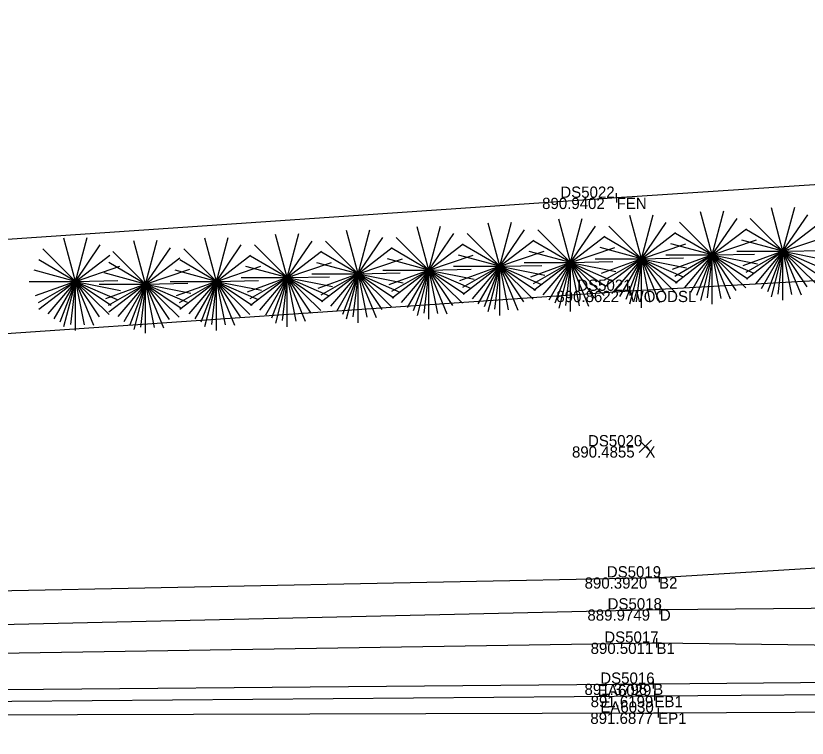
# Model space of a CAD drawing. Extents: x 179044 to 189691, y 286531 to 301257.
# Drawn here: x 179702.4 to 179786.9, y 300591.8 to 300668.9 of the extents above; entities that cross this region are included whole.
import ezdxf

# ---------------------------------------------------------------- set-up
doc = ezdxf.new("R2010")
doc.units = 0
for name, color, linetype in [('DR_X_Ditch', 7, 'Continuous'), ('PV_X_EOP', 7, 'Continuous'), ('PV_X_Shoulder_Aggregate', 7, 'Continuous'), ('RD_X_Fence', 7, 'Continuous'), ('SV_X_Break_Lines', 7, 'Continuous'), ('SV_X_Random_Point', 7, 'Continuous'), ('SV_X_Shot_Marker', 7, 'Continuous'), ('SV_X_Text_Comment', 7, 'Continuous'), ('SV_X_Text_Elevation', 7, 'Continuous'), ('SV_X_Text_Name', 7, 'Continuous'), ('VG_X_Cells', 7, 'Continuous'), ('VG_X_Text', 7, 'Continuous'), ('VG_X_Tree_Line_Rt', 7, 'Continuous')]:
    doc.layers.add(name, color=color, linetype=linetype)

msp = doc.modelspace()

# ---------------------------------------------------------------- linework, layer by layer
at = {"layer": 'DR_X_Ditch'}
msp.add_lwpolyline([(179564.56, 300599.962), (179672.339, 300603.26), (179771.172, 300605.494), (179880.337, 300606.441), (179984.937, 300607.328), (180077.947, 300608.965), (180127.19, 300616.843), (180132.045, 300619.573), (180144.286, 300623.545), (180155.547, 300629.29), (180160.465, 300633.547)], dxfattribs=at)
at = {"layer": 'PV_X_EOP'}
msp.add_lwpolyline([(179370.831, 300591.751), (179475.585, 300592.875), (179659.265, 300594.122), (179770.991, 300594.472), (179880.742, 300594.985), (179984.71, 300595.495), (180079.288, 300595.313), (180129.921, 300597.382), (180139.474, 300598.239), (180154.233, 300602.666), (180170.463, 300611.587), (180179.633, 300620.691), (180184.59, 300626.615), (180188.342, 300633.535), (180190.62, 300639.725), (180171.316, 300693.382), (180137.201, 300785.062), (180098.417, 300888.791)], dxfattribs=at)
at = {"layer": 'PV_X_Shoulder_Aggregate'}
msp.add_lwpolyline([(179563.565, 300594.924), (179658.987, 300595.359), (179770.596, 300596.259), (179881.565, 300597.129), (179984.257, 300597.357), (180079.139, 300597.322), (180129.307, 300600.299), (180139.964, 300601.425), (180153.02, 300605.118), (180169.97, 300613.883), (180177.635, 300623.691), (180181.654, 300635.111), (180182.998, 300649.235), (180167.771, 300692.69), (180134.639, 300784.201), (180095.484, 300888.508)], dxfattribs=at)
at = {"layer": 'RD_X_Fence'}
msp.add_lwpolyline([(180033.616, 300896.161), (180069.423, 300800.637), (180103.118, 300709.458), (180117.129, 300674.9), (180112.616, 300673.011), (180037.359, 300667.77), (179974.547, 300663.799), (179875.902, 300656.609), (179766.558, 300649.439), (179668.068, 300642.7), (179565.54, 300636.358)], dxfattribs=at)
at = {"layer": 'SV_X_Break_Lines'}
for points in [[(179564.638, 300606.986), (179671.768, 300606.922), (179771.087, 300608.912), (179880.599, 300615.611), (179986.884, 300616.02), (180078.033, 300615.521), (180124.742, 300624.492), (180128.289, 300624.221), (180137.303, 300629.118), (180148.459, 300633.708), (180154.503, 300636.496), (180146.307, 300651.241), (180135.969, 300673.811), (180118.542, 300716.074), (180095.911, 300772.35), (180076.611, 300824.96), (180047.5, 300900.199)], [(179564.191, 300598.682), (179770.809, 300601.942), (179880.33, 300600.557), (179984.707, 300602.17), (180076.298, 300602.513), (180129.447, 300605.473), (180133.823, 300610.665), (180143.543, 300612.063), (180154.911, 300619.358), (180168.807, 300625.749), (180172.898, 300631.66), (180174.527, 300641.071), (180168.307, 300660.619), (180157.537, 300688.57), (180123.865, 300779.294), (180087.271, 300883.216)], [(179564.385, 300595.92), (179672.75, 300596.68), (179770.459, 300597.562), (179880.51, 300598.544), (179984.703, 300599.007), (180076.342, 300598.773), (180129.476, 300602.027), (180135.94, 300603.814), (180151.807, 300606.879), (180162.976, 300612.722)]]:
    msp.add_lwpolyline(points, dxfattribs=at)
at = {"layer": 'SV_X_Random_Point'}
for p, q in [((179768.958, 300622.237), (179770.291, 300623.572)), ((179768.958, 300623.572), (179770.291, 300622.237))]:
    msp.add_line(p, q, dxfattribs=at)
at = {"layer": 'SV_X_Shot_Marker'}
for p, q in [((179766.591, 300648.94), (179766.526, 300649.938)), ((179767.057, 300649.471), (179766.059, 300649.406)), ((179766.558, 300649.439), (179766.558, 300649.439)), ((179767.436, 300639.47), (179768.434, 300639.538)), ((179767.901, 300640.003), (179767.969, 300639.005)), ((179767.935, 300639.504), (179767.935, 300639.504)), ((179770.587, 300608.902), (179771.587, 300608.922)), ((179771.077, 300609.412), (179771.097, 300608.412)), ((179771.087, 300608.912), (179771.087, 300608.912)), ((179771.161, 300605.994), (179771.183, 300604.994)), ((179770.672, 300605.483), (179771.672, 300605.505)), ((179771.172, 300605.494), (179771.172, 300605.494)), ((179770.801, 300602.442), (179770.816, 300601.442)), ((179770.309, 300601.934), (179771.309, 300601.95)), ((179770.809, 300601.942), (179770.809, 300601.942)), ((179770.454, 300598.062), (179770.463, 300597.062)), ((179769.959, 300597.558), (179770.959, 300597.567)), ((179770.459, 300597.562), (179770.459, 300597.562)), ((179770.096, 300596.255), (179771.096, 300596.263)), ((179770.592, 300596.759), (179770.6, 300595.759)), ((179770.596, 300596.259), (179770.596, 300596.259)), ((179770.99, 300594.972), (179770.993, 300593.972)), ((179770.491, 300594.47), (179771.491, 300594.474)), ((179770.991, 300594.472), (179770.991, 300594.472))]:
    msp.add_line(p, q, dxfattribs=at)
at = {"layer": 'VG_X_Cells'}
for p, q in [((179776.76, 300643.334), (179775.525, 300647.947)), ((179776.76, 300643.334), (179778.016, 300648.032)), ((179784.326, 300643.736), (179783.091, 300648.35)), ((179784.326, 300643.736), (179785.582, 300648.435)), ((179761.627, 300642.529), (179760.392, 300647.143)), ((179761.627, 300642.529), (179762.884, 300647.228)), ((179769.193, 300642.932), (179767.958, 300647.545)), ((179769.193, 300642.932), (179770.45, 300647.63)), ((179776.76, 300643.334), (179779.415, 300647.219)), ((179784.326, 300643.736), (179780.836, 300647.223)), ((179784.326, 300643.736), (179786.981, 300647.621)), ((179746.495, 300641.725), (179745.26, 300646.338)), ((179746.495, 300641.725), (179747.752, 300646.423)), ((179754.061, 300642.127), (179752.826, 300646.74)), ((179754.061, 300642.127), (179755.318, 300646.825)), ((179761.627, 300642.529), (179764.282, 300646.414)), ((179769.193, 300642.932), (179765.703, 300646.418)), ((179769.193, 300642.932), (179771.848, 300646.817)), ((179776.76, 300643.334), (179773.27, 300646.821)), ((179776.76, 300643.334), (179780.416, 300646.139)), ((179784.326, 300643.736), (179787.982, 300646.541)), ((179731.363, 300640.92), (179730.128, 300645.533)), ((179731.363, 300640.92), (179732.62, 300645.618)), ((179738.929, 300641.322), (179737.694, 300645.936)), ((179738.929, 300641.322), (179740.186, 300646.021)), ((179746.495, 300641.725), (179749.15, 300645.61)), ((179754.061, 300642.127), (179750.571, 300645.614)), ((179754.061, 300642.127), (179756.716, 300646.012)), ((179761.627, 300642.529), (179758.137, 300646.016)), ((179761.627, 300642.529), (179765.284, 300645.334)), ((179769.193, 300642.932), (179772.85, 300645.737)), ((179776.76, 300643.334), (179772.853, 300645.631)), ((179784.326, 300643.736), (179780.419, 300646.033)), ((179784.326, 300643.736), (179789.062, 300645.343)), ((179708.74, 300640.517), (179707.505, 300645.131)), ((179708.74, 300640.517), (179709.997, 300645.216)), ((179716.224, 300640.227), (179714.989, 300644.841)), ((179716.224, 300640.227), (179717.48, 300644.926)), ((179723.797, 300640.518), (179722.562, 300645.131)), ((179723.797, 300640.518), (179725.054, 300645.216)), ((179731.363, 300640.92), (179727.873, 300644.407)), ((179731.363, 300640.92), (179734.018, 300644.805)), ((179738.929, 300641.322), (179735.439, 300644.809)), ((179738.929, 300641.322), (179741.584, 300645.207)), ((179746.495, 300641.725), (179743.005, 300645.211)), ((179746.495, 300641.725), (179750.152, 300644.53)), ((179754.061, 300642.127), (179750.154, 300644.424)), ((179754.061, 300642.127), (179757.718, 300644.932)), ((179761.627, 300642.529), (179757.72, 300644.826)), ((179769.193, 300642.932), (179765.287, 300645.228)), ((179769.193, 300642.932), (179773.93, 300644.538)), ((179776.76, 300643.334), (179772.346, 300644.517)), ((179776.76, 300643.334), (179781.496, 300644.941)), ((179784.326, 300643.736), (179779.912, 300644.92)), ((179708.74, 300640.517), (179705.25, 300644.004)), ((179708.74, 300640.517), (179711.395, 300644.402)), ((179716.224, 300640.227), (179712.734, 300643.714)), ((179716.224, 300640.227), (179718.879, 300644.112)), ((179723.797, 300640.518), (179720.307, 300644.005)), ((179723.797, 300640.518), (179726.452, 300644.403)), ((179731.363, 300640.92), (179735.02, 300643.725)), ((179738.929, 300641.322), (179735.022, 300643.619)), ((179738.929, 300641.322), (179742.586, 300644.127)), ((179746.495, 300641.725), (179742.588, 300644.021)), ((179754.061, 300642.127), (179758.798, 300643.734)), ((179761.627, 300642.529), (179757.214, 300643.713)), ((179761.627, 300642.529), (179766.364, 300644.136)), ((179769.193, 300642.932), (179764.78, 300644.115)), ((179779.391, 300643.736), (179784.326, 300643.736)), ((179784.326, 300643.736), (179780.036, 300642.175)), ((179784.326, 300643.736), (179780.342, 300641.455)), ((179784.326, 300643.736), (179780.419, 300640.741)), ((179784.326, 300643.736), (179781.381, 300640.27)), ((179784.326, 300643.736), (179782.007, 300639.721)), ((179784.326, 300643.736), (179782.661, 300639.396)), ((179784.326, 300643.736), (179783.062, 300638.88)), ((179784.326, 300643.736), (179783.784, 300639.145)), ((179784.326, 300643.736), (179788.836, 300643.828)), ((179784.326, 300638.496), (179784.326, 300643.736)), ((179784.326, 300643.736), (179785.247, 300639.1)), ((179784.326, 300643.736), (179786.259, 300639.068)), ((179784.326, 300643.736), (179786.862, 300639.943)), ((179784.326, 300643.736), (179787.914, 300640.215)), ((179784.326, 300643.736), (179788.147, 300641.181)), ((179784.326, 300643.736), (179788.791, 300641.795)), ((179784.326, 300643.736), (179789.154, 300642.778)), ((179708.74, 300640.517), (179704.834, 300642.814)), ((179708.74, 300640.517), (179712.397, 300643.322)), ((179716.224, 300640.227), (179719.88, 300643.032)), ((179723.797, 300640.518), (179719.891, 300642.815)), ((179723.797, 300640.518), (179727.454, 300643.323)), ((179731.363, 300640.92), (179727.456, 300643.217)), ((179738.929, 300641.322), (179743.666, 300642.929)), ((179746.495, 300641.725), (179742.082, 300642.908)), ((179746.495, 300641.725), (179751.232, 300643.331)), ((179754.061, 300642.127), (179749.648, 300643.31)), ((179764.258, 300642.932), (179769.193, 300642.932)), ((179769.193, 300642.932), (179764.903, 300641.37)), ((179769.193, 300642.932), (179765.21, 300640.65)), ((179769.193, 300642.932), (179765.287, 300639.937)), ((179769.193, 300642.932), (179766.248, 300639.465)), ((179769.193, 300642.932), (179766.875, 300638.917)), ((179769.193, 300642.932), (179767.528, 300638.592)), ((179769.193, 300642.932), (179767.93, 300638.075)), ((179769.193, 300642.932), (179768.652, 300638.34)), ((179769.193, 300642.932), (179773.703, 300643.023)), ((179769.193, 300637.692), (179769.193, 300642.932)), ((179769.193, 300642.932), (179770.115, 300638.295)), ((179769.193, 300642.932), (179771.127, 300638.263)), ((179769.193, 300642.932), (179771.73, 300639.138)), ((179769.193, 300642.932), (179772.782, 300639.41)), ((179769.193, 300642.932), (179773.015, 300640.377)), ((179769.193, 300642.932), (179773.658, 300640.99)), ((179769.193, 300642.932), (179774.022, 300641.973)), ((179771.825, 300643.334), (179776.76, 300643.334)), ((179776.76, 300643.334), (179772.47, 300641.772)), ((179776.76, 300643.334), (179772.776, 300641.052)), ((179776.76, 300643.334), (179772.853, 300640.339)), ((179776.76, 300643.334), (179773.815, 300639.867)), ((179776.76, 300643.334), (179774.441, 300639.319)), ((179776.76, 300643.334), (179775.095, 300638.994)), ((179776.76, 300643.334), (179775.496, 300638.477)), ((179776.76, 300643.334), (179776.218, 300638.742)), ((179776.76, 300643.334), (179781.27, 300643.426)), ((179776.76, 300638.094), (179776.76, 300643.334)), ((179776.76, 300643.334), (179777.681, 300638.697)), ((179776.76, 300643.334), (179778.693, 300638.666)), ((179776.76, 300643.334), (179779.296, 300639.541)), ((179776.76, 300643.334), (179780.348, 300639.812)), ((179776.76, 300643.334), (179780.581, 300640.779)), ((179776.76, 300643.334), (179781.225, 300641.392)), ((179776.76, 300643.334), (179781.588, 300642.376)), ((179708.74, 300640.517), (179713.477, 300642.124)), ((179716.224, 300640.227), (179712.317, 300642.524)), ((179723.797, 300640.518), (179728.534, 300642.125)), ((179731.363, 300640.92), (179726.95, 300642.103)), ((179731.363, 300640.92), (179736.1, 300642.527)), ((179738.929, 300641.322), (179734.516, 300642.506)), ((179749.126, 300642.127), (179754.061, 300642.127)), ((179754.061, 300642.127), (179749.771, 300640.565)), ((179754.061, 300642.127), (179750.078, 300639.845)), ((179754.061, 300642.127), (179750.154, 300639.132)), ((179754.061, 300642.127), (179751.116, 300638.66)), ((179754.061, 300642.127), (179751.743, 300638.112)), ((179754.061, 300642.127), (179752.396, 300637.787)), ((179754.061, 300642.127), (179752.798, 300637.27)), ((179754.061, 300642.127), (179753.519, 300637.535)), ((179754.061, 300642.127), (179758.571, 300642.219)), ((179754.061, 300636.887), (179754.061, 300642.127)), ((179754.061, 300642.127), (179754.983, 300637.49)), ((179754.061, 300642.127), (179755.994, 300637.459)), ((179754.061, 300642.127), (179756.598, 300638.334)), ((179754.061, 300642.127), (179757.649, 300638.605)), ((179754.061, 300642.127), (179757.883, 300639.572)), ((179754.061, 300642.127), (179758.526, 300640.185)), ((179754.061, 300642.127), (179758.889, 300641.169)), ((179756.692, 300642.529), (179761.627, 300642.529)), ((179761.627, 300642.529), (179757.337, 300640.968)), ((179761.627, 300642.529), (179757.644, 300640.248)), ((179761.627, 300642.529), (179757.72, 300639.534)), ((179761.627, 300642.529), (179758.682, 300639.063)), ((179761.627, 300642.529), (179759.309, 300638.514)), ((179761.627, 300642.529), (179759.962, 300638.189)), ((179761.627, 300642.529), (179760.364, 300637.673)), ((179761.627, 300642.529), (179761.085, 300637.938)), ((179761.627, 300642.529), (179766.137, 300642.621)), ((179761.627, 300637.289), (179761.627, 300642.529)), ((179761.627, 300642.529), (179762.549, 300637.893)), ((179761.627, 300642.529), (179763.56, 300637.861)), ((179761.627, 300642.529), (179764.164, 300638.736)), ((179761.627, 300642.529), (179765.215, 300639.008)), ((179761.627, 300642.529), (179765.449, 300639.974)), ((179761.627, 300642.529), (179766.092, 300640.588)), ((179761.627, 300642.529), (179766.455, 300641.571)), ((179708.74, 300640.517), (179704.327, 300641.701)), ((179716.224, 300640.227), (179711.81, 300641.411)), ((179716.224, 300640.227), (179720.96, 300641.834)), ((179723.797, 300640.518), (179719.384, 300641.701)), ((179733.994, 300641.322), (179738.929, 300641.322)), ((179738.929, 300641.322), (179734.639, 300639.761)), ((179738.929, 300641.322), (179734.946, 300639.041)), ((179738.929, 300641.322), (179735.022, 300638.327)), ((179738.929, 300641.322), (179735.984, 300637.856)), ((179738.929, 300641.322), (179736.611, 300637.307)), ((179738.929, 300641.322), (179737.264, 300636.982)), ((179738.929, 300641.322), (179737.666, 300636.466)), ((179738.929, 300641.322), (179738.387, 300636.731)), ((179738.929, 300641.322), (179743.439, 300641.414)), ((179738.929, 300636.082), (179738.929, 300641.322)), ((179738.929, 300641.322), (179739.851, 300636.686)), ((179738.929, 300641.322), (179740.862, 300636.654)), ((179738.929, 300641.322), (179741.466, 300637.529)), ((179738.929, 300641.322), (179742.517, 300637.801)), ((179738.929, 300641.322), (179742.751, 300638.767)), ((179738.929, 300641.322), (179743.394, 300639.381)), ((179738.929, 300641.322), (179743.757, 300640.364)), ((179741.56, 300641.725), (179746.495, 300641.725)), ((179746.495, 300641.725), (179742.205, 300640.163)), ((179746.495, 300641.725), (179742.512, 300639.443)), ((179746.495, 300641.725), (179742.588, 300638.73)), ((179746.495, 300641.725), (179743.55, 300638.258)), ((179746.495, 300641.725), (179744.177, 300637.71)), ((179746.495, 300641.725), (179744.83, 300637.385)), ((179746.495, 300641.725), (179745.232, 300636.868)), ((179746.495, 300641.725), (179745.953, 300637.133)), ((179746.495, 300641.725), (179751.005, 300641.816)), ((179746.495, 300636.485), (179746.495, 300641.725)), ((179746.495, 300641.725), (179747.417, 300637.088)), ((179746.495, 300641.725), (179748.428, 300637.056)), ((179746.495, 300641.725), (179749.032, 300637.931)), ((179746.495, 300641.725), (179750.083, 300638.203)), ((179746.495, 300641.725), (179750.317, 300639.17)), ((179746.495, 300641.725), (179750.96, 300639.783)), ((179746.495, 300641.725), (179751.323, 300640.766)), ((179703.805, 300640.517), (179708.74, 300640.517)), ((179708.74, 300640.517), (179704.45, 300638.956)), ((179708.74, 300640.517), (179704.757, 300638.236)), ((179708.74, 300640.517), (179704.834, 300637.522)), ((179708.74, 300640.517), (179705.795, 300637.051)), ((179708.74, 300640.517), (179706.422, 300636.502)), ((179708.74, 300640.517), (179707.075, 300636.177)), ((179708.74, 300640.517), (179707.477, 300635.661)), ((179708.74, 300640.517), (179708.199, 300635.926)), ((179708.74, 300640.517), (179713.25, 300640.609)), ((179708.74, 300635.277), (179708.74, 300640.517)), ((179708.74, 300640.517), (179709.662, 300635.881)), ((179708.74, 300640.517), (179710.674, 300635.849)), ((179708.74, 300640.517), (179711.277, 300636.724)), ((179708.74, 300640.517), (179712.329, 300636.996)), ((179708.74, 300640.517), (179712.562, 300637.962)), ((179708.74, 300640.517), (179713.205, 300638.576)), ((179708.74, 300640.517), (179713.569, 300639.559)), ((179711.289, 300640.227), (179716.224, 300640.227)), ((179716.224, 300640.227), (179711.934, 300638.666)), ((179716.224, 300640.227), (179712.24, 300637.946)), ((179716.224, 300640.227), (179712.317, 300637.232)), ((179716.224, 300640.227), (179713.279, 300636.761)), ((179716.224, 300640.227), (179713.905, 300636.212)), ((179716.224, 300640.227), (179714.559, 300635.887)), ((179716.224, 300640.227), (179714.96, 300635.371)), ((179716.224, 300640.227), (179715.682, 300635.636)), ((179716.224, 300640.227), (179720.734, 300640.319)), ((179716.224, 300634.987), (179716.224, 300640.227)), ((179716.224, 300640.227), (179717.145, 300635.591)), ((179716.224, 300640.227), (179718.157, 300635.559)), ((179716.224, 300640.227), (179718.76, 300636.434)), ((179716.224, 300640.227), (179719.812, 300636.706)), ((179716.224, 300640.227), (179720.045, 300637.672)), ((179716.224, 300640.227), (179720.689, 300638.286)), ((179716.224, 300640.227), (179721.052, 300639.269)), ((179718.862, 300640.518), (179723.797, 300640.518)), ((179723.797, 300640.518), (179719.507, 300638.956)), ((179723.797, 300640.518), (179719.814, 300638.236)), ((179723.797, 300640.518), (179719.891, 300637.523)), ((179723.797, 300640.518), (179720.852, 300637.051)), ((179723.797, 300640.518), (179721.479, 300636.503)), ((179723.797, 300640.518), (179722.132, 300636.178)), ((179723.797, 300640.518), (179722.534, 300635.661)), ((179723.797, 300640.518), (179723.256, 300635.926)), ((179723.797, 300640.518), (179728.307, 300640.61)), ((179723.797, 300635.278), (179723.797, 300640.518)), ((179723.797, 300640.518), (179724.719, 300635.881)), ((179723.797, 300640.518), (179725.731, 300635.85)), ((179723.797, 300640.518), (179726.334, 300636.725)), ((179723.797, 300640.518), (179727.386, 300636.996)), ((179723.797, 300640.518), (179727.619, 300637.963)), ((179723.797, 300640.518), (179728.262, 300638.576)), ((179723.797, 300640.518), (179728.626, 300639.56)), ((179726.428, 300640.92), (179731.363, 300640.92)), ((179731.363, 300640.92), (179727.073, 300639.358)), ((179731.363, 300640.92), (179727.38, 300638.638)), ((179731.363, 300640.92), (179727.456, 300637.925)), ((179731.363, 300640.92), (179728.418, 300637.453)), ((179731.363, 300640.92), (179729.045, 300636.905)), ((179731.363, 300640.92), (179729.698, 300636.58)), ((179731.363, 300640.92), (179730.1, 300636.063)), ((179731.363, 300640.92), (179730.821, 300636.328)), ((179731.363, 300640.92), (179735.873, 300641.012)), ((179731.363, 300635.68), (179731.363, 300640.92)), ((179731.363, 300640.92), (179732.285, 300636.283)), ((179731.363, 300640.92), (179733.296, 300636.252)), ((179731.363, 300640.92), (179733.9, 300637.127)), ((179731.363, 300640.92), (179734.951, 300637.398)), ((179731.363, 300640.92), (179735.185, 300638.365)), ((179731.363, 300640.92), (179735.828, 300638.978)), ((179731.363, 300640.92), (179736.191, 300639.962))]:
    msp.add_line(p, q, dxfattribs=at)
at = {"layer": 'VG_X_Tree_Line_Rt'}
msp.add_lwpolyline([(179653.026, 300638.702), (179657.624, 300631.959), (179767.935, 300639.504), (179876.981, 300645.549), (179982.655, 300652.223), (180074.045, 300659.112), (180113.167, 300662.01), (180119.55, 300662.124), (180124.383, 300666.201), (180126.147, 300679.098), (180114.54, 300714.374), (180093.362, 300771.604), (180073.514, 300824.308), (180043.465, 300899.612)], dxfattribs=at)

# ---------------------------------------------------------------- texts
at = {"layer": 'SV_X_Text_Comment'}
for s, height, p in [('FEN', 1.2, (179766.558, 300648.239)), ('TE', 0.12, (179784.326, 300643.616)), ('TE', 0.12, (179769.193, 300642.812)), ('TE', 0.12, (179776.76, 300643.214)), ('TE', 0.12, (179754.061, 300642.007)), ('TE', 0.12, (179761.627, 300642.409)), ('TE', 0.12, (179738.929, 300641.202)), ('TE', 0.12, (179746.495, 300641.605)), ('TE', 0.12, (179708.74, 300640.397)), ('TE', 0.12, (179716.224, 300640.107)), ('TE', 0.12, (179723.797, 300640.398)), ('TE', 0.12, (179731.363, 300640.8)), ('WOODSL', 1.2, (179767.935, 300638.304)), ('X', 1.2, (179769.625, 300621.704)), ('B2', 1.2, (179771.087, 300607.712)), ('D', 1.2, (179771.172, 300604.294)), ('B1', 1.2, (179770.809, 300600.742)), ('B', 1.2, (179770.459, 300596.362)), ('EB1', 1.2, (179770.596, 300595.059)), ('EP1', 1.2, (179770.991, 300593.272))]:
    msp.add_text(s, height=height, dxfattribs=at).set_placement(p)
at = {"layer": 'SV_X_Text_Elevation'}
for s, p in [('890.9402', (179758.594, 300648.239)), ('890.8622', (179760.112, 300638.304)), ('890.4855', (179761.783, 300621.704)), ('890.3920', (179763.132, 300607.712)), ('889.9749', (179763.434, 300604.294)), ('890.5011', (179763.773, 300600.742)), ('891.3796', (179763.118, 300596.362)), ('891.6199', (179763.775, 300595.059)), ('891.6877', (179763.745, 300593.272))]:
    msp.add_text(s, height=1.2, dxfattribs=at).set_placement(p)
at = {"layer": 'SV_X_Text_Name'}
for s, p in [('DS5022', (179760.54, 300649.439)), ('DS5021', (179762.345, 300639.504)), ('DS5020', (179763.493, 300622.904)), ('DS5019', (179765.504, 300608.912)), ('DS5018', (179765.589, 300605.494)), ('DS5017', (179765.235, 300601.942)), ('DS5016', (179764.809, 300597.562)), ('EA6029', (179764.549, 300596.259)), ('EA6030', (179764.812, 300594.472))]:
    msp.add_text(s, height=1.2, dxfattribs=at).set_placement(p)
at = {"layer": 'VG_X_Text'}
for p in [(179784.326, 300643.736), (179769.193, 300642.932), (179776.76, 300643.334), (179754.061, 300642.127), (179761.627, 300642.529), (179731.363, 300640.92), (179738.929, 300641.322), (179746.495, 300641.725), (179708.74, 300640.517), (179716.224, 300640.227), (179723.797, 300640.518)]:
    msp.add_text(' NOTE:8', height=0.12, dxfattribs=at).set_placement(p)

doc.saveas('drawing.dxf')
